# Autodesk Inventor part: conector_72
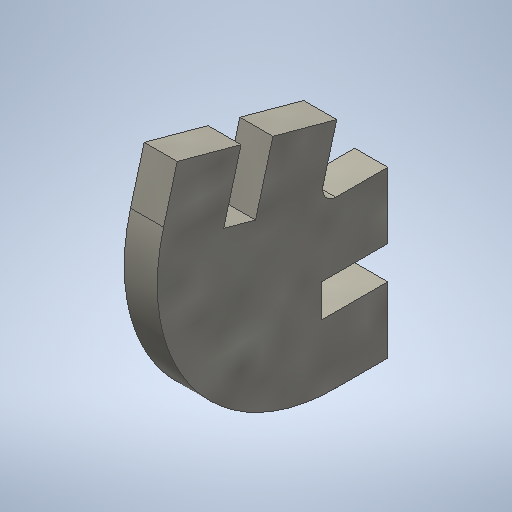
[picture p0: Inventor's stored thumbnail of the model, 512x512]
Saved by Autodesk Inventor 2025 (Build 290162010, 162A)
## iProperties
Created: 2025-02
Part Number: conector_72
Material: Paper
Document SubType Name: Modeling
Designer: BennF
Density: 0.93 g/cm^3
Appearance: Cardboard - Chipboard
Author: BennF
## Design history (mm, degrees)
sketch "Sketch2"
  geometry: L1 (0, -1)-(3.93, -1); L2 (3.93, -1)-(3.93, -6); L3 (3.93, -6)-(-1.07, -6); L4 (-1.07, -6)-(-1.07, -8.5); L5 (-1.07, -8.5)-(3.93, -8.5); L6 (3.93, -8.5)-(3.93, -13.5); L7 (3.93, -13.5)-(0, -13.5); L8 (-13.025, 3.551)-(-11.991, 7.342); L9 (-11.991, 7.342)-(-7.167, 6.027); L10 (-7.167, 6.027)-(-8.482, 1.203); L11 (-8.482, 1.203)-(-6.07, 0.546); L12 (-6.07, 0.546)-(-4.755, 5.37); L13 (-4.755, 5.37)-(0.069, 4.054); L14 (0.069, 4.054)-(-0.965, 0.263); L15 (-6.07, 0.546)-(-1.07, -6); A1 r 1 centre (0, 0) between (-0.965, 0.263) and (0, -1); A2 r 13.5 centre (0, 0) between (-13.025, 3.551) and (0, -13.5); 1 further point
  constraints: 30 end point, 10 perpendicular, 7 equal length, 4 point on circle, 4 point on line, 2 centre point, 2 coincident, 2 tangent, 1 horizontal
  dimensions: "d0" = 2.5 distance of L3.end L4.end (= thickness); "d1" = 5 distance of L2.end L3.end (= slot_depth); "d2" = 5 distance of L5.end L6.end (= slot_dis_1); "d3" = 74.75 deg angle of L1 L14 (= con_angle_6); "d4" = 1 radius of A1; "d5" = 5 horizontal distance of L11.end L3.end (computed from slot_clearenece)
extrude "Extrusion1" new body sketch "Sketch2" distance "d6" = 2.5 (= thickness); taper "d7" = 0 deg
sketch "laser"
  geometry: L1 (13.5, 0)-(13.5, 3.93) reference; L2 (13.5, 3.93)-(8.5, 3.93) reference; L3 (8.5, 3.93)-(8.5, -1.07) reference; L4 (8.5, -1.07)-(6, -1.07) reference; L5 (6, -1.07)-(6, 3.93) reference; L6 (6, 3.93)-(1, 3.93) reference; L7 (1, 3.93)-(1, 0) reference; L8 (-0.263, -0.965)-(-4.054, 0.069) reference; L9 (-4.054, 0.069)-(-5.37, -4.755) reference; L10 (-5.37, -4.755)-(-0.546, -6.07) reference; L11 (-0.546, -6.07)-(-1.203, -8.482) reference; L12 (-1.203, -8.482)-(-6.027, -7.167) reference; L13 (-6.027, -7.167)-(-7.342, -11.991) reference; L14 (-7.342, -11.991)-(-3.551, -13.025) reference; A1 r 1 centre (0, 0) between (-0.263, -0.965) and (1, 0) reference; A2 r 13.5 centre (0, 0) between (-3.551, -13.025) and (13.5, 0) reference; 1 further point
  node "Projected Loop1"
body "Solid1"
other parameters: "thickness" = 2.5 [user parameter; used in 2 equation terms], "clearence" = -0.5 [user parameter], "slot_depth" = 5 [user parameter; used in 1 equation term], "slot_dis_1" = 5 [user parameter; used in 1 equation term], "slot_dis_2" = 12 [user parameter], "slot_clearenece" = 3 [user parameter; used in 1 equation term], "con_angle_1" = 20.34444 [user parameter], "con_angle_2" = 60 deg [user parameter], "con_angle_3" = 12.30959 [user parameter], "con_angle_4" = 19.10633 [user parameter], "con_angle_5" = 24.11865 [user parameter], "con_angle_6" = 74.75 deg [user parameter; used in 1 equation term]
